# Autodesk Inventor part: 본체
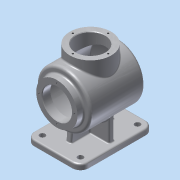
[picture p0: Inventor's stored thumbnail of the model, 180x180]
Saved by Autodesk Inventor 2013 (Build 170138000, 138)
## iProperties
Created: 2016-09
Part Number: 본체
Material: 알루미늄 6061
Document SubType Name: Modeling
Designer: Administrator
Density: 2.71 g/cm^3
Mass: 970.774 g
Surface Area: 1285.08 cm^2
Volume: 358.219 cm^3
Author: Administrator
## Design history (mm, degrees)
sketch "스케치1"
  geometry: L1 (-67.5, 50)-(67.5, 50); L2 (67.5, 50)-(67.5, -50); L3 (67.5, -50)-(-67.5, -50); L4 (-67.5, -50)-(-67.5, 50); 3 further points
  constraints: 8 end point, 2 midpoint, 2 parallel, 1 horizontal, 1 horizontal alignment, 1 perpendicular, 1 vertical alignment
  dimensions: "d0" = 135 distance of L2.end L3.end; "d1" = 100 distance of L1.end L2.end
extrude "돌출1" new body sketch "스케치1" distance "d2" = 10; taper "d3" = 0 deg
sketch "스케치2"
  geometry: L1 (-61, 82)-(61, 82); L2 (-67.5, 0)-(67.5, 0) reference; L3 (-61, 82)-(-61, 120); L4 (-61, 120)-(-49, 120); L5 (-49, 120)-(-49, 132); L6 (-49, 132)-(49.562, 132); A1 r 115 centre (-54, 82) between (61, 82) and (49.562, 132); 3 further points
  constraints: 10 end point, 2 midpoint, 2 parallel, 2 perpendicular, 2 point on circle, 1 centre point, 1 horizontal, 1 point on line, 1 vertical alignment
  dimensions: "d4" = 122 distance of L1.start L1.end; "d5" = 82 distance between parallel lines of L2 L1; "d6" = 12 distance between parallel lines of L5 L3; "d8" = 115 radius of A1; "d9" = 100 diameter of L6 L1; "d10" = 76 diameter of L4 L1
revolve "회전1" stored, may be unused: angle "d11" = 90 deg
sketch "스케치3"
  geometry: L1 (67.5, 10)-(-67.5, 10) reference; L2 (-40, 10)-(-33.701, 82); L3 (-33.701, 82)-(33.701, 82); L4 (33.701, 82)-(40, 10); L5 (-67.5, 0)-(67.5, 0) reference; 2 further points
  constraints: 6 end point, 2 point on line, 1 equal length, 1 horizontal, 1 midpoint, 1 vertical alignment
  dimensions: "d12" = 95 deg angle of L2 L1; "d13" = 82 distance between parallel lines of L5 L3; "d14" = 40 horizontal distance of point (0, 0) L2.start
extrude "돌출2" join sketch "스케치3" stored distance "d15" = 10; taper "d16" = 0 deg
sketch "스케치4"
  geometry: L1 (50, 10)-(-50, 10) reference; L2 (-40, 10)-(-40, 82); L3 (-40, 82)-(40, 82); L4 (40, 82)-(40, 10); L5 (-50, 0)-(50, 0) reference; 2 further points
  constraints: 6 end point, 2 parallel, 2 point on line, 1 midpoint, 1 vertical alignment
  dimensions: "d18" = 40 distance from line of point (0, 0) L2; "d19" = 82 distance between parallel lines of L5 L3
extrude "돌출3" join sketch "스케치4" stored distance "d20" = 10; taper "d21" = 0 deg
node "작업 평면1"
sketch "스케치5"
  geometry: L1 (49, 50)-(49, -50) reference; C1 r 38 at (-1, 0); 1 further point
  constraints: 1 centre point, 1 horizontal alignment
  dimensions: "d23" = 76 diameter of C1; "d24" = 50 distance from line of C1.centre L1
extrude "돌출4" join sketch "스케치5" distance "d25" = 50; taper "d26" = 0 deg
sketch "스케치6"
  geometry: L1 (-61, 82)-(61, 82) reference; L2 (-61, 82)-(-61, 120) reference; L3 (-49, 132)-(49.562, 132) reference; L4 (-49, 120)-(-49, 132) reference; L5 (-61, 120)-(-49, 120) reference; L6 (-46, 82)-(-46, 129); L7 (-46, 129)-(47.661, 129); A1 r 115 centre (-54, 82) between (61, 82) and (49.562, 132) reference; A2 r 112 centre (-54, 82) between (58, 82) and (47.661, 129); 1 further point
  constraints: 4 end point, 2 point on circle, 2 point on line, 1 centre point, 1 other
  dimensions: "d27" = 3 distance between parallel lines of L7 L3; "d28" = 3 radial gap between concentric circles of A1 A2
revolve "회전2" sketch "스케치6" stored, may be unused: angle "d29" = 90 deg
hole "구멍1" diameter "d32" = 54; stored, may be unused: countersink angle "d36" = 90 deg, drill point angle "d38" = 0 deg; dims "d30" = 10, "d31" = 10, "d33" = 6, "d34" = 4, "d35" = 2, "d37" = 50
hole "구멍2" diameter "d41" = 54; stored, may be unused: countersink angle "d45" = 90 deg, drill point angle "d47" = 0 deg; dims "d39" = 10, "d40" = 10, "d42" = 6, "d43" = 4, "d44" = 2, "d46" = 50
sketch "스케치7"
  geometry: C1 r 50 at (0, 0) reference; A1 r 32.5 centre (0, 0) between (-32.5, 0) and (32.5, 0); 3 further points
  constraints: 4 point on circle, 2 horizontal alignment, 2 vertical alignment, 1 centre point, 1 coincident
  dimensions: "d48" = 65 diameter of A1
hole "구멍3" sketch "스케치7" at (-32.5, 0), (32.5, 0), (0, -32.5), (0, 32.5) diameter "d49" = 3.242; stored, may be unused: countersink angle "d53" = 90 deg, drill point angle "d55" = 118 deg; dims "d50" = 8, "d51" = 4, "d52" = 2, "d54" = 10
sketch "스케치8"
  geometry: C1 r 27 at (0, 0) reference; C2 r 38 at (0, 0) reference; A1 r 32.5 centre (0, 0) between (0, 32.5) and (-32.5, 0); 3 further points
  constraints: 4 point on circle, 2 horizontal alignment, 2 vertical alignment, 1 centre point, 1 coincident
  dimensions: "d56" = 65 diameter of A1
hole "구멍4" sketch "스케치8" at (0, 32.5), (-32.5, 0), (0, -32.5), (32.5, 0) diameter "d57" = 3.242; stored, may be unused: countersink angle "d61" = 90 deg, drill point angle "d63" = 118 deg; dims "d58" = 8, "d59" = 4, "d60" = 2, "d62" = 10
fillet "모깎기1" dims "d64" = 15
hole "구멍5" diameter "d67" = 10; stored, may be unused: countersink angle "d71" = 90 deg, drill point angle "d73" = 0 deg; dims "d65" = 10, "d66" = 10, "d68" = 8, "d69" = 4, "d70" = 2, "d72" = 10
hole "구멍6" diameter "d76" = 10; stored, may be unused: countersink angle "d80" = 90 deg, drill point angle "d82" = 0 deg; dims "d74" = 10, "d75" = 10, "d77" = 8, "d78" = 4, "d79" = 2, "d81" = 10
hole "구멍7" diameter "d85" = 10; stored, may be unused: countersink angle "d89" = 90 deg, drill point angle "d91" = 0 deg; dims "d83" = 10, "d84" = 10, "d86" = 8, "d87" = 4, "d88" = 2, "d90" = 10
hole "구멍8" diameter "d94" = 10; stored, may be unused: countersink angle "d98" = 90 deg, drill point angle "d100" = 0 deg; dims "d92" = 10, "d93" = 10, "d95" = 8, "d96" = 4, "d97" = 2, "d99" = 10
fillet "모깎기2" dims "d101" = 5
fillet "모깎기3" dims "d102" = 2
chamfer "모따기1" distance "d103" = 1; stored, may be unused: second distance "d104" = 2, angle "d105" = 45 deg
fillet "모깎기4" dims "d106" = 3
fillet "모깎기5" dims "d107" = 3
fillet "모깎기6" dims "d108" = 3
fillet "모깎기7" dims "d109" = 3
fillet "모깎기8" dims "d110" = 3
fillet "모깎기9" dims "d113" = 2
node "솔리드1"
node "투영된 루프1"
other parameters: "d22" = 147
